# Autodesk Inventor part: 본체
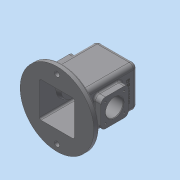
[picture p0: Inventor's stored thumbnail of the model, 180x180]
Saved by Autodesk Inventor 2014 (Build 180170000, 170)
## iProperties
Created: 2021-08
Part Number: 본체
Material: 일반
Document SubType Name: Modeling
Designer: dg
Density: 1 g/cm^3
Appearance: 기본값
Author: dg
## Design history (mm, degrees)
sketch "스케치1"
  geometry: L1 (37, -37)-(-37, -37); L2 (-37, -37)-(-37, 37); L3 (-37, 37)-(37, 37); L4 (37, 37)-(37, -37); 3 further points
  constraints: 8 end point, 2 midpoint, 2 parallel, 1 horizontal, 1 horizontal alignment, 1 perpendicular, 1 vertical alignment
  dimensions: "d0" = 74 distance of L1.start L1.end; "d1" = 74 distance of L1.end L2.end
extrude "돌출1" new body sketch "스케치1" distance "d2" = 100; taper "d3" = 0 deg
sketch "스케치2"
  geometry: C1 r 67 at (0, 0); 1 further point
  constraints: 1 centre point, 1 coincident
  dimensions: "d4" = 134 diameter of C1
extrude "돌출2" join sketch "스케치2" distance "d5" = 10; taper "d6" = 0 deg
sketch "스케치3"
  geometry: L1 (-32, 32)-(32, 32); L2 (32, 32)-(32, -32); L3 (32, -32)-(-32, -32); L4 (-32, -32)-(-32, 32); L5 (37, 37)-(-37, 37) reference; C1 r 67 at (0, 0) reference; 2 further points
  constraints: 8 end point, 2 midpoint, 2 parallel, 1 horizontal, 1 horizontal alignment, 1 perpendicular, 1 vertical alignment
  dimensions: "d7" = 64 distance of L1.start L1.end; "d8" = 64 distance of L1.end L2.end
extrude "돌출3" cut sketch "스케치3" distance "d9" = 105; taper "d10" = 0 deg
sketch "스케치4"
  geometry: L1 (100, 37)-(100, -37) reference; L2 (100, 0)-(110, 0); L3 (110, 0)-(110, 20); L4 (110, 20)-(100, 21.051); L5 (0, 37)-(100, 37) reference; L6 (100, 21.051)-(100, 0); 1 further point
  constraints: 8 end point, 3 perpendicular, 1 midpoint, 1 point on line
  dimensions: "d11" = 10 distance of L2.start L2.end; "d12" = 20 distance of L2.end L3.end; "d13" = 6 deg angle of L4 L5
revolve "회전1" sketch "스케치4" stored, may be unused: angle "d14" = 90 deg
hole "구멍1" diameter "d17" = 21; stored, may be unused: countersink angle "d21" = 90 deg, drill point angle "d23" = 118 deg; dims "d15" = 10, "d16" = 10, "d18" = 6, "d19" = 28, "d20" = 4, "d22" = 50
sketch "스케치5"
  geometry: L1 (74, -100)-(0, -100) reference; L2 (12, -30)-(62, -30); L3 (62, -30)-(62, -80); L4 (62, -80)-(12, -80); L5 (12, -80)-(12, -30); L6 (-30, -110)-(104, -110) reference; 4 further points
  constraints: 8 end point, 3 midpoint, 2 parallel, 1 horizontal, 1 perpendicular, 1 vertical alignment
  dimensions: "d24" = 50 distance of L2.start L2.end; "d25" = 50 distance of L4.end L2.start; "d26" = 55 distance from line of L6 point (62, -55)
extrude "돌출4" join sketch "스케치5" distance "d27" = 13; taper "d28" = 0 deg
sketch "스케치6"
  geometry: L1 (-32, -10)-(-32, 95) reference; L2 (-32, 45)-(-25, 45); L3 (32, -10)-(-32, -10) reference; L4 (-32, 45)-(-32, 70); L5 (-25, 45)-(-25, 67.452); L6 (-25, 67.452)-(-32, 70); 1 further point
  constraints: 8 end point, 2 point on line, 1 parallel, 1 perpendicular
  dimensions: "d29" = 7 distance of L2.start L2.end; "d30" = 55 distance between parallel lines of L2 L3; "d31" = 25 distance of L2.start L4.end; "d32" = 110 deg angle of L6 L1
revolve "회전2" sketch "스케치6" stored, may be unused: angle "d33" = 90 deg
sketch "스케치7"
  geometry: L1 (0, 50)-(50, 50) reference; L2 (50, 50)-(50, 0) reference; 4 further points
  constraints: 2 midpoint, 1 horizontal alignment, 1 vertical alignment
hole "구멍2" sketch "스케치7" at (25, 25) diameter "d34" = 32; stored, may be unused: countersink angle "d38" = 90 deg, drill point angle "d40" = 118 deg; dims "d35" = 6, "d36" = 28, "d37" = 4, "d39" = 100
fillet "모깎기1" dims "d41" = 8
fillet "모깎기2" dims "d42" = 8
fillet "모깎기3" dims "d43" = 3
fillet "모깎기4" dims "d44" = 3
chamfer "모따기1" distance "d45" = 1; stored, may be unused: second distance "d46" = 2, angle "d47" = 45 deg
fillet "모깎기5" dims "d48" = 8
fillet "모깎기6" dims "d49" = 3
fillet "모깎기7" dims "d50" = 3
sketch "스케치8"
  geometry: L1 (-8, 92)-(-8, 0) reference; L2 (49, 110)-(9, 110) reference; 2 further points
  constraints: 1 other
  dimensions: "d51" = 37 distance from line of L1 point (29, 82); "d52" = 28 distance from line of point (29, 82) L2
feature "엠보싱1" sketch "스케치8" dims "d0" = 74, "d1" = 74, "d53" = 0.5, "d54" = 0
fillet "모깎기8" dims "d55" = 3
fillet "모깎기9" dims "d56" = 3
sketch "스케치9"
  geometry: C1 r 64 at (0, 0) reference; 1 further point
  constraints: 1 vertical alignment
  dimensions: "d57" = 55 distance of point (0, -55) C1.centre
hole "구멍3" sketch "스케치9" at (0, -55) diameter "d58" = 9; stored, may be unused: countersink angle "d62" = 90 deg, drill point angle "d64" = 118 deg; dims "d59" = 6, "d60" = 28, "d61" = 4, "d63" = 100
hole "구멍4" diameter "d70" = 3.242; stored, may be unused: countersink angle "d74" = 90 deg, drill point angle "d76" = 118 deg; dims "d68" = 10, "d69" = 10, "d71" = 6, "d72" = 28, "d73" = 4, "d75" = 8
node "솔리드1"
mirror "대칭1"
mirror "대칭2"
pattern_circular "원형 패턴1" dims angle "d66" = 360 deg
pattern_linear "직사각형 패턴1" dims "d79" = 34
pattern_linear "직사각형 패턴2" dims "d82" = 34
mirror "대칭3"
